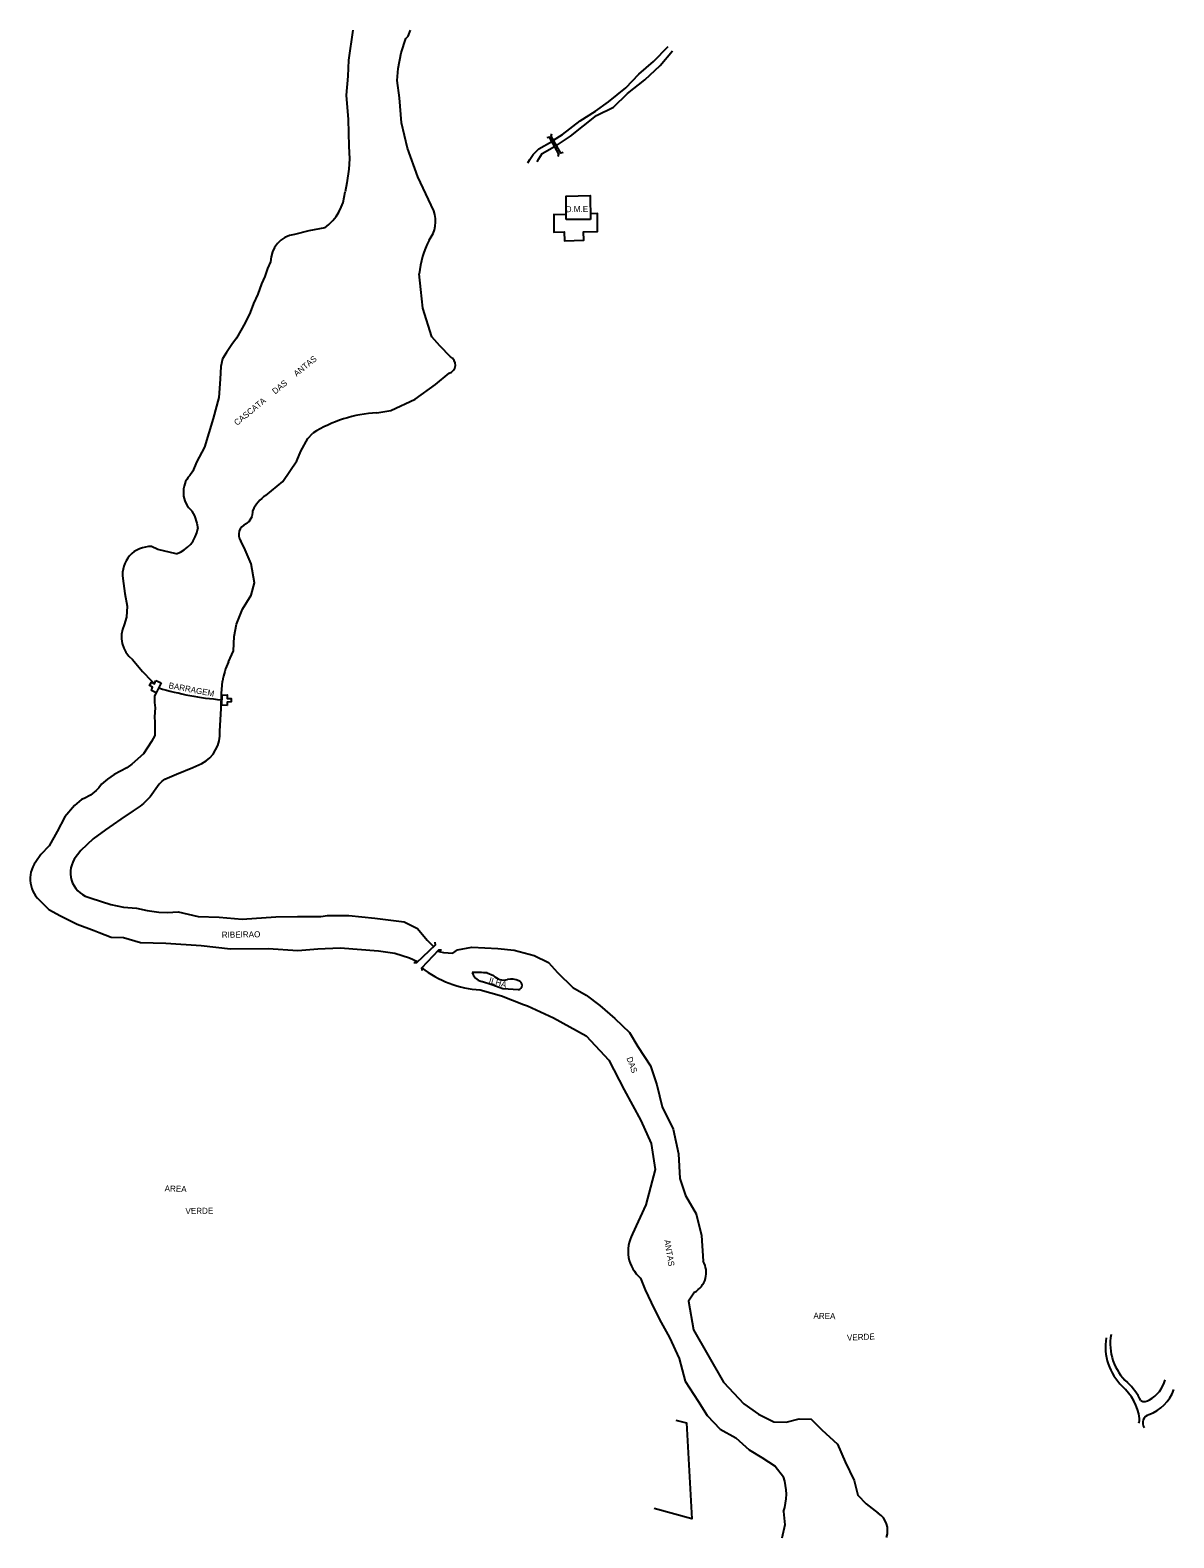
# Model space of a CAD drawing. Extents: x 325899 to 364828, y 7568995 to 7592502.
# Drawn here: x 333745 to 334503, y 7591502 to 7592502 of the extents above; entities that cross this region are included whole.
import ezdxf

# ---------------------------------------------------------------- set-up
doc = ezdxf.new("R2010")
doc.units = 0
for name, color, linetype in [('EDIFEXISTENT', 7, 'Continuous'), ('EDIFIDENTIF', 7, 'Continuous'), ('EDIFOBRAEXIS', 7, 'Continuous')]:
    doc.layers.add(name, color=color, linetype=linetype)

msp = doc.modelspace()

# ---------------------------------------------------------------- linework, layer by layer
at = {"layer": 'EDIFEXISTENT'}
for points in [[(334098.74, 7592420.75), (334096.98, 7592420.4), (334090.65, 7592431.7), (334091.21, 7592433.18)], [(334095.27, 7592418.19), (334095.82, 7592419.69), (334089.48, 7592430.91), (334087.7, 7592430.61)], [(334100.71, 7592376.37), (334100.67, 7592391.94), (334116.54, 7592392.19), (334116.71, 7592376.32)], [(334100.7, 7592379.44), (334092.45, 7592379.63), (334092.52, 7592367.91), (334099.4, 7592368.18), (334099.41, 7592362.31), (334112.27, 7592362.65), (334112.21, 7592368.09), (334121.45, 7592368.47), (334121.35, 7592377.48), (334121.35, 7592380.27), (334116.66, 7592380.14)], [(334116.71, 7592376.32), (334100.71, 7592376.37)], [(333832.23, 7592069.06), (333829.02, 7592062.51), (333825.75, 7592064.15), (333826.53, 7592066.29), (333824.58, 7592067.3), (333825.82, 7592069.63), (333827.74, 7592068.57), (333828.74, 7592070.62)], [(333828.74, 7592070.62), (333832.23, 7592069.06)], [(333872.48, 7592054.29), (333872.56, 7592060.88), (333875.88, 7592061.17), (333875.96, 7592058.86), (333878.61, 7592058.76), (333878.52, 7592056.46), (333875.92, 7592056.42), (333876.03, 7592054.1)], [(333876.03, 7592054.1), (333872.48, 7592054.29)], [(334013.56, 7591897.22), (334013.73, 7591895.24), (334001.42, 7591883.47), (333999.67, 7591883.52)], [(334005.2, 7591878.4), (334004.94, 7591880.18), (334016.32, 7591892.19), (334018.02, 7591892.09)]]:
    msp.add_lwpolyline(points, dxfattribs=at)
msp.add_arc((333888.58, 7592258.38), 201.11, 253.25105, 265.3133, dxfattribs=at)
at = {"layer": 'EDIFOBRAEXIS'}
for points in [[(333959.26, 7592501.91), (333956.41, 7592482.1), (333955.93, 7592471.46), (333954.91, 7592458.89), (333956.06, 7592442.77), (333956.5, 7592424.93), (333957.11, 7592416.63), (333956.58, 7592409.77), (333955.3, 7592400.66), (333954.08, 7592394.7)], [(334012.94, 7592382.15), (334002.37, 7592404.64), (333995.41, 7592423.59), (333991.41, 7592440.36), (333990.15, 7592457.03), (333988.62, 7592468.55), (333989.19, 7592476.41), (333991.24, 7592486.94), (333994.27, 7592496.27), (333995.87, 7592497.98), (333997.41, 7592501.91)], [(334092.25, 7592428.97), (334098.24, 7592432.68), (334109.79, 7592441.87), (334119.96, 7592448.14), (334128.63, 7592454.29), (334140.23, 7592463.71), (334148.72, 7592472.65), (334158.43, 7592481.21), (334168.15, 7592491)], [(334094.16, 7592425.48), (334103.42, 7592431.54), (334120.75, 7592445.41), (334131.96, 7592450.93), (334141.28, 7592459.95), (334152.74, 7592468.97), (334162.89, 7592478.58), (334171.07, 7592488.29)], [(334075.14, 7592413.95), (334076.58, 7592416.25), (334078.67, 7592419.52), (334082.43, 7592423.23), (334091.04, 7592428.07)], [(334081.39, 7592414.58), (334082.48, 7592416.52), (334084.8, 7592420.19), (334092.95, 7592424.76)], [(333940.61, 7592370.92), (333930.13, 7592368.87), (333920.58, 7592366.5)], [(333904.72, 7592348.34), (333902.8, 7592343.89), (333900.89, 7592338.47), (333898.69, 7592333.74), (333896.24, 7592326.82), (333893.51, 7592320.64), (333891.17, 7592314.71), (333887.96, 7592307.84), (333882.21, 7592297.77), (333879.04, 7592293.48), (333875.51, 7592288.09), (333872.93, 7592284.01), (333871.87, 7592278.88), (333871.39, 7592270.42), (333870.47, 7592258.23), (333866.76, 7592244.44), (333860.94, 7592225.33), (333855.58, 7592215.47), (333853.15, 7592209.47), (333851.16, 7592206.71)], [(334023.96, 7592285.34), (334016.98, 7592292.63), (334011.65, 7592298.54), (334005.62, 7592317.48), (334005.62, 7592317.48), (334004.26, 7592329.97), (334003.2, 7592340.39)], [(333975.18, 7592248.08), (333984.43, 7592249.68), (334000.46, 7592257.21), (334014.05, 7592267), (334023.02, 7592274.5)], [(333901.52, 7592193.31), (333912.8, 7592202.58), (333922.06, 7592216.34), (333924.89, 7592222.85), (333929.38, 7592231.08), (333932.78, 7592234.67)], [(333852.63, 7592183.08), (333854.36, 7592179.91), (333855.88, 7592175.07), (333856.48, 7592171.48)], [(333876.85, 7592083.06), (333880.1, 7592090.26), (333880.55, 7592099.97), (333882.05, 7592107.98), (333886.21, 7592118.03), (333891.79, 7592127.29), (333894.1, 7592135.44), (333891.78, 7592147.95), (333887.32, 7592158.96), (333884.94, 7592163.13)], [(333842.2, 7592154.75), (333830.12, 7592157.62), (333825.84, 7592159.45)], [(333806.9, 7592138.36), (333808.13, 7592128.4), (333809.78, 7592119.89), (333809.15, 7592112.79), (333807.62, 7592107.63)], [(333813.23, 7592084.61), (333819.78, 7592076.76), (333825.83, 7592070.53), (333827.74, 7592068.57)], [(333871.01, 7592037.19), (333871.92, 7592052.14), (333872.31, 7592062.02), (333872.77, 7592070.18)], [(333829.02, 7592062.51), (333827.74, 7592060.55), (333827.77, 7592056), (333828.24, 7592052.66), (333827.88, 7592046.63), (333827.95, 7592043.04), (333828.02, 7592039.67), (333828.03, 7592034.3), (333825.93, 7592030.2), (333820.55, 7592022.06), (333812.86, 7592015.19), (333809.42, 7592012.89), (333801.02, 7592008.36), (333796.61, 7592005.29), (333792.69, 7592001.91)], [(333830.91, 7592001.91), (333832.85, 7592003.92), (333834.75, 7592005.25), (333842.46, 7592008.57), (333853.3, 7592012.93), (333859.14, 7592015.66)], [(333792.69, 7592001.91), (333790.97, 7591999.45), (333789.16, 7591997.84), (333785.29, 7591994.62), (333781.1, 7591992.55), (333779.48, 7591991.82), (333774.87, 7591987.75), (333768.41, 7591980.39), (333763.22, 7591970.6), (333758.07, 7591961.02), (333752.4, 7591955.22), (333749.1, 7591950.5)], [(333830.91, 7592001.91), (333824.96, 7591993.5), (333820.48, 7591989.23), (333818.28, 7591987.43), (333813.6, 7591984.23), (333805.5, 7591978.68), (333795.27, 7591971.57), (333787.19, 7591965.68), (333779.01, 7591957.98), (333774.63, 7591952.14)], [(333753.02, 7591923.8), (333757.72, 7591918.8), (333765.49, 7591914.74), (333776.67, 7591909.2), (333787.93, 7591904.87), (333791.13, 7591903.57), (333799.1, 7591900.47), (333807.35, 7591900.29), (333818.43, 7591897.03), (333835.22, 7591896.6), (333858.83, 7591894.95), (333878.15, 7591892.67), (333903.11, 7591892.9), (333922.85, 7591891.75), (333936.13, 7591892.69), (333950.86, 7591893.48), (333976.19, 7591891.5), (333987.04, 7591889.99), (333996.7, 7591886.7), (334002.11, 7591884.27)], [(333785.81, 7591926.46), (333798.95, 7591922.08), (333807.26, 7591920.45), (333815.92, 7591919.7), (333823.06, 7591918.14), (333830.75, 7591917.15), (333836.5, 7591916.87), (333843.6, 7591917.34), (333856.7, 7591914.15), (333870.75, 7591913.66), (333885.91, 7591912.45), (333908.12, 7591914.03), (333922.49, 7591914.25), (333938.04, 7591914.19), (333942.45, 7591914.82), (333956.54, 7591914.86), (333973.89, 7591913.01), (333993.36, 7591910.6), (334002.17, 7591906.21), (334008.53, 7591898.52), (334012.65, 7591894.36)], [(334015.33, 7591891.14), (334019.34, 7591890.27), (334022.45, 7591890.13), (334025.44, 7591889.97), (334028.66, 7591892.2), (334038.03, 7591893.8), (334055.37, 7591893.04), (334066.24, 7591891.78), (334079.52, 7591888.27), (334088.96, 7591883.76), (334094.8, 7591876.97), (334105.05, 7591867.11), (334113.83, 7591862.03), (334122.86, 7591855.2), (334132.8, 7591846.6), (334142.58, 7591837.26), (334148.11, 7591827.91), (334156.55, 7591815.26), (334160.72, 7591802.64), (334164.35, 7591787.98), (334171.45, 7591773.22), (334174.98, 7591756.94), (334175.93, 7591740.56), (334179.69, 7591729.24), (334186.77, 7591717.06), (334190.41, 7591702.78), (334191.42, 7591685.62)], [(334048.37, 7591876.85), (334052.47, 7591875.15)], [(334043.58, 7591865.64), (334057.72, 7591861.7), (334072.28, 7591855.81), (334075.08, 7591854.94), (334092.12, 7591847.01), (334113.88, 7591835.08), (334128.81, 7591818.87), (334138.97, 7591799.36), (334150.1, 7591779.02), (334156.86, 7591763.71), (334159.65, 7591746.45), (334153.39, 7591723.13), (334144.62, 7591703.74)], [(334068.94, 7591865.53), (334058.61, 7591866.3), (334051.26, 7591868.91), (334044.46, 7591871.22)], [(334149.99, 7591674.41), (334152.92, 7591666.59), (334159.01, 7591654), (334163.6, 7591644.95), (334169.05, 7591635), (334175.45, 7591621.18), (334179.56, 7591606.13), (334188.12, 7591592.9), (334193.97, 7591583.27), (334202.7, 7591574.34), (334212.95, 7591568.51), (334221.84, 7591560.56), (334230.31, 7591555.59), (334239.23, 7591549.85), (334244.59, 7591542.59)], [(334185.76, 7591665.07), (334181.7, 7591659.15), (334184.95, 7591640.11), (334194.53, 7591623.59), (334204.85, 7591605.42), (334218.47, 7591591.01), (334228.06, 7591584.27), (334238.32, 7591579.21), (334246.35, 7591578.91), (334255.07, 7591581.2), (334262.92, 7591580.87), (334269.99, 7591573.94), (334280.33, 7591564.23), (334285.54, 7591552.56), (334291.41, 7591540.17), (334293.97, 7591530.54), (334299.39, 7591524.84), (334307.49, 7591518.58)], [(334173.39, 7591580.21), (334180.38, 7591578.44), (334183.92, 7591514.81), (334158.94, 7591521.64)], [(334244.66, 7591519.61), (334244.66, 7591519.61), (334244.66, 7591519.61), (334245.45, 7591510.76), (334243.57, 7591501.91)]]:
    msp.add_lwpolyline(points, dxfattribs=at)
for centre, radius, start, end in [((333922.07, 7592397.12), 32.09, 305.27977, 355.67799), ((333993.73, 7592375.26), 20.41, 321.72573, 19.74169), ((333923.13, 7592348.27), 18.41, 97.94911, 179.79016), ((334064.32, 7592334.47), 61.4, 152.71119, 174.46697), ((334021.37, 7592280.1), 5.84, 286.38654, 63.7604), ((333979.07, 7592162.08), 86.09, 92.58741, 122.52324), ((333863.54, 7592195.62), 16.62, 138.14791, 228.96963), ((333913.74, 7592174.13), 22.74, 122.50995, 155.78253), ((333883.19, 7592182.76), 9.83, 302.48861, 4.06173), ((333891.13, 7592167.42), 7.53, 110.65591, 214.68016), ((333836.22, 7592174.33), 20.47, 287.00031, 352.00867), ((333824.87, 7592141.27), 18.2, 86.93727, 189.19666), ((333825.06, 7592099.69), 19.17, 155.52307, 231.88641), ((333926.25, 7592060.35), 54.37, 155.30794, 169.58549), ((333848.89, 7592035.35), 22.2, 297.50044, 4.7609), ((333764.73, 7591939.16), 19.31, 144.04448, 232.69848), ((333789.28, 7591943.25), 17.14, 148.74255, 258.33542), ((334047.43, 7591934.46), 68.93, 231.95039, 266.80182), ((334036.51, 7591611.94), 265.17, 87.43704, 89.61002), ((334046.82, 7591879.83), 8.93, 197.76426, 254.67722), ((334059.31, 7591881.26), 9.17, 221.77544, 285.96943), ((334064.35, 7591860.89), 11.82, 65.65493, 102.26952), ((334068.23, 7591868.63), 3.18, 282.87273, 71.83069), ((334165.03, 7591692.31), 23.38, 150.76084, 229.96738), ((334178.46, 7591678.14), 14.96, 299.16396, 29.99854), ((334494.82, 7591629.17), 36.84, 170.98339, 225.84953), ((334495.71, 7591630.84), 34.54, 169.52837, 227.93275), ((334444.35, 7591575.66), 36.74, 8.93416, 47.50067), ((334444.7, 7591575.35), 40.83, 26.02972, 46.97407), ((334476.85, 7591612.65), 21.51, 298.69303, 344.77745), ((334483.92, 7591597.67), 5.08, 240.14621, 309.90949), ((334477.49, 7591609.64), 27.38, 289.91075, 340.56589), ((334488.38, 7591578.45), 5.66, 106.02687, 214.51389), ((334474.12, 7591580.65), 6.55, 338.13026, 6.22978), ((334210.91, 7591531), 35.62, 341.34503, 18.98233), ((334299.68, 7591506.97), 13.99, 341.48561, 56.09351)]:
    msp.add_arc(centre, radius, start, end, dxfattribs=at)

# ---------------------------------------------------------------- texts
at = {"layer": 'EDIFIDENTIF'}
for s, rotation, p in [('D.M.E', 0.67596, (334100.36, 7592381.2)), ('CASCATA     DAS     ANTAS', 39.45896, (333882.54, 7592239.47)), ('BARRAGEM', 349.34685, (333836.91, 7592065.59)), ('RIBEIRAO', 0.6563, (333872.4, 7591900.14)), ('ILHA', 343.62717, (334049.09, 7591870.23)), ('DAS', 289.76915, (334140.54, 7591820.32)), ('AREA', 358.03344, (333834.48, 7591731.98)), ('VERDE', 0.69562, (333848.35, 7591716.94)), ('ANTAS', 279.63862, (334165.57, 7591699.55)), ('AREA', 358.85188, (334264.45, 7591647.49)), ('VERDE', 2.64975, (334286.8, 7591632.96))]:
    msp.add_text(s, height=4, rotation=rotation, dxfattribs=at).set_placement(p)

doc.saveas('drawing.dxf')
